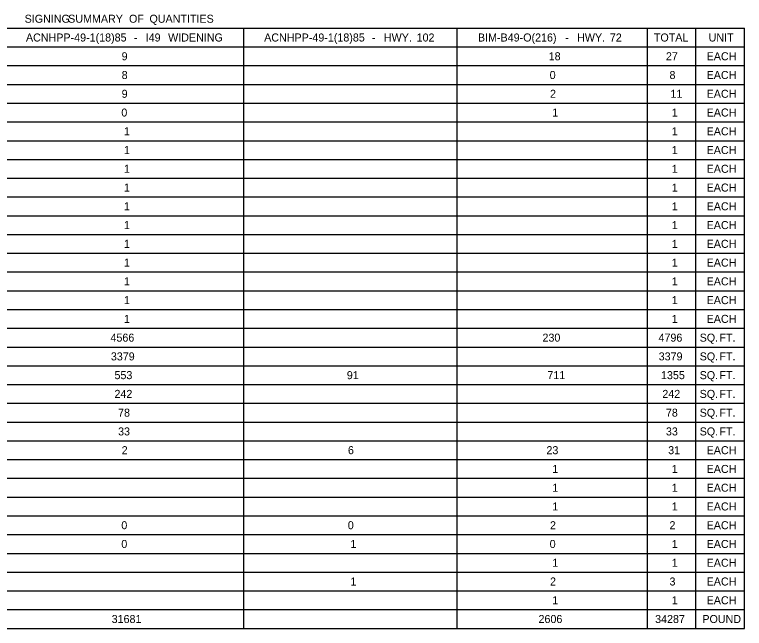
# Model space of a CAD drawing. Extents: x 1226631 to 1228126, y 151309 to 152305.
# Drawn here: x 1227282.4 to 1227738, y 151311 to 151693.8 of the extents above; entities that cross this region are included whole.
import ezdxf

# ---------------------------------------------------------------- set-up
doc = ezdxf.new("R2010")
doc.units = 0
doc.layers.add('R_Dimension', color=7, linetype='Continuous')

msp = doc.modelspace()

# ---------------------------------------------------------------- linework, layer by layer
at = {"layer": 'R_Dimension'}
for p, q in [((1226960.39, 151685.37), (1227737.95, 151685.37)), ((1227425.47, 151310.97), (1227425.47, 151685.37)), ((1227558.55, 151310.97), (1227558.55, 151685.37)), ((1227677.5, 151310.97), (1227677.5, 151685.37)), ((1227707.73, 151310.97), (1227707.73, 151685.37)), ((1227737.95, 151310.97), (1227737.95, 151685.37)), ((1226960.39, 151673.67), (1227737.95, 151673.67)), ((1226960.39, 151661.97), (1227737.95, 151661.97)), ((1226960.39, 151650.27), (1227737.95, 151650.27)), ((1226960.39, 151638.57), (1227737.95, 151638.57)), ((1226960.39, 151626.87), (1227737.95, 151626.87)), ((1226960.39, 151615.17), (1227737.95, 151615.17)), ((1226960.39, 151603.47), (1227737.95, 151603.47)), ((1226960.39, 151591.77), (1227737.95, 151591.77)), ((1226960.39, 151580.07), (1227737.95, 151580.07)), ((1226960.39, 151568.37), (1227737.95, 151568.37)), ((1226960.39, 151556.67), (1227737.95, 151556.67)), ((1226960.39, 151544.97), (1227737.95, 151544.97)), ((1226960.39, 151533.27), (1227737.95, 151533.27)), ((1226960.39, 151521.57), (1227737.95, 151521.57)), ((1226960.39, 151509.87), (1227737.95, 151509.87)), ((1226960.39, 151498.17), (1227737.95, 151498.17)), ((1226960.39, 151486.47), (1227737.95, 151486.47)), ((1226960.39, 151474.77), (1227737.95, 151474.77)), ((1226960.39, 151463.07), (1227737.95, 151463.07)), ((1226960.39, 151451.37), (1227737.95, 151451.37)), ((1226960.39, 151439.67), (1227737.95, 151439.67)), ((1226960.39, 151427.97), (1227737.95, 151427.97)), ((1226960.39, 151416.27), (1227737.95, 151416.27)), ((1226960.39, 151404.57), (1227737.95, 151404.57)), ((1226960.39, 151392.87), (1227737.95, 151392.87)), ((1226960.39, 151381.17), (1227737.95, 151381.17)), ((1226960.39, 151369.47), (1227737.95, 151369.47)), ((1226960.39, 151357.77), (1227737.95, 151357.77)), ((1226960.39, 151346.07), (1227737.95, 151346.07)), ((1226960.39, 151334.37), (1227737.95, 151334.37)), ((1226960.39, 151322.67), (1227737.95, 151322.67)), ((1226960.39, 151310.97), (1227737.95, 151310.97))]:
    msp.add_line(p, q, dxfattribs=at)

# ---------------------------------------------------------------- texts
for s, p in [('SIGNING', (1227288.64, 151688.72)), (' SUMMARY', (1227313.96, 151688.72)), (' OF', (1227351.95, 151688.72)), (' QUANTITIES', (1227364.71, 151688.72)), ('ACNHPP-49-1(18)85', (1227289.47, 151677.02)), (' I49', (1227362.35, 151677.02)), (' WIDENING', (1227376.36, 151677.02)), ('ACNHPP-49-1(18)85', (1227438.17, 151677.02)), (' HWY.', (1227511.05, 151677.02)), (' 102', (1227531.48, 151677.02)), ('BIM-B49-O(216)', (1227571.63, 151677.02)), (' HWY.', (1227631.67, 151677.02)), (' 72', (1227652.1, 151677.02)), ('TOTAL', (1227681.44, 151677.02)), ('UNIT', (1227715.62, 151677.02)), (' -', (1227354.91, 151677.02)), (' -', (1227503.61, 151677.02)), (' -', (1227624.23, 151677.02)), ('9', (1227349.2, 151665.32)), ('18', (1227615.79, 151665.32)), ('27', (1227688.96, 151665.32)), ('EACH', (1227714.38, 151665.32)), ('8', (1227349.22, 151653.62)), ('0', (1227616.4, 151653.62)), ('8', (1227691.2, 151653.62)), ('EACH', (1227714.38, 151653.62)), ('9', (1227349.2, 151641.92)), ('2', (1227616.61, 151641.92)), ('11', (1227691.79, 151641.92)), ('EACH', (1227714.38, 151641.92)), ('0', (1227349, 151630.22)), ('1', (1227618.03, 151630.22)), ('1', (1227692.62, 151630.22)), ('EACH', (1227714.38, 151630.22)), ('1', (1227350.64, 151618.52)), ('1', (1227692.62, 151618.52)), ('EACH', (1227714.38, 151618.52)), ('1', (1227350.64, 151606.82)), ('1', (1227692.62, 151606.82)), ('EACH', (1227714.38, 151606.82)), ('1', (1227350.64, 151595.12)), ('1', (1227692.62, 151595.12)), ('EACH', (1227714.38, 151595.12)), ('1', (1227350.64, 151583.42)), ('1', (1227692.62, 151583.42)), ('EACH', (1227714.38, 151583.42)), ('1', (1227350.64, 151571.72)), ('1', (1227692.62, 151571.72)), ('EACH', (1227714.38, 151571.72)), ('1', (1227350.64, 151560.02)), ('1', (1227692.62, 151560.02)), ('EACH', (1227714.38, 151560.02)), ('1', (1227350.64, 151548.32)), ('1', (1227692.62, 151548.32)), ('EACH', (1227714.38, 151548.32)), ('1', (1227350.64, 151536.62)), ('1', (1227692.62, 151536.62)), ('EACH', (1227714.38, 151536.62)), ('1', (1227350.64, 151524.92)), ('1', (1227692.62, 151524.92)), ('EACH', (1227714.38, 151524.92)), ('1', (1227350.64, 151513.22)), ('1', (1227692.62, 151513.22)), ('EACH', (1227714.38, 151513.22)), ('1', (1227350.64, 151501.52)), ('1', (1227692.62, 151501.52)), ('EACH', (1227714.38, 151501.52)), ('4566', (1227342.23, 151489.82)), ('230', (1227611.91, 151489.82)), ('4796', (1227684.33, 151489.82)), ('SQ.', (1227710.03, 151489.82)), (' FT.', (1227720.5, 151489.82)), ('3379', (1227342.47, 151478.12)), ('3379', (1227684.45, 151478.12)), ('SQ.', (1227710.03, 151478.12)), (' FT.', (1227720.5, 151478.12)), ('553', (1227344.73, 151466.42)), ('91', (1227489.77, 151466.42)), ('711', (1227614.96, 151466.42)), ('1355', (1227685.89, 151466.42)), ('SQ.', (1227710.03, 151466.42)), (' FT.', (1227720.5, 151466.42)), ('242', (1227344.73, 151454.72)), ('242', (1227686.71, 151454.72)), ('SQ.', (1227710.03, 151454.72)), (' FT.', (1227720.5, 151454.72)), ('78', (1227346.97, 151443.02)), ('78', (1227688.96, 151443.02)), ('SQ.', (1227710.03, 151443.02)), (' FT.', (1227720.5, 151443.02)), ('33', (1227346.97, 151431.32)), ('33', (1227688.96, 151431.32)), ('SQ.', (1227710.03, 151431.32)), (' FT.', (1227720.5, 151431.32)), ('2', (1227349.22, 151419.62)), ('6', (1227490.46, 151419.62)), ('23', (1227614.37, 151419.62)), ('31', (1227690.37, 151419.62)), ('EACH', (1227714.38, 151419.62)), ('1', (1227618.03, 151407.92)), ('1', (1227692.62, 151407.92)), ('EACH', (1227714.38, 151407.92)), ('1', (1227618.03, 151396.22)), ('1', (1227692.62, 151396.22)), ('EACH', (1227714.38, 151396.22)), ('1', (1227618.03, 151384.52)), ('1', (1227692.62, 151384.52)), ('EACH', (1227714.38, 151384.52)), ('0', (1227349, 151372.82)), ('0', (1227490.38, 151372.82)), ('2', (1227616.61, 151372.82)), ('2', (1227691.2, 151372.82)), ('EACH', (1227714.38, 151372.82)), ('0', (1227349, 151361.12)), ('1', (1227492.01, 151361.12)), ('0', (1227616.4, 151361.12)), ('1', (1227692.62, 151361.12)), ('EACH', (1227714.38, 151361.12)), ('1', (1227618.03, 151349.42)), ('1', (1227692.62, 151349.42)), ('EACH', (1227714.38, 151349.42)), ('1', (1227492.01, 151337.72)), ('2', (1227616.61, 151337.72)), ('3', (1227691.2, 151337.72)), ('EACH', (1227714.38, 151337.72)), ('1', (1227618.03, 151326.02)), ('1', (1227692.62, 151326.02)), ('EACH', (1227714.38, 151326.02)), ('31681', (1227342.96, 151314.32)), ('2606', (1227609.43, 151314.32)), ('34287', (1227682.22, 151314.32)), ('POUND', (1227711.72, 151314.32))]:
    msp.add_text(s, height=5, dxfattribs=at).set_placement(p)

doc.saveas('drawing.dxf')
